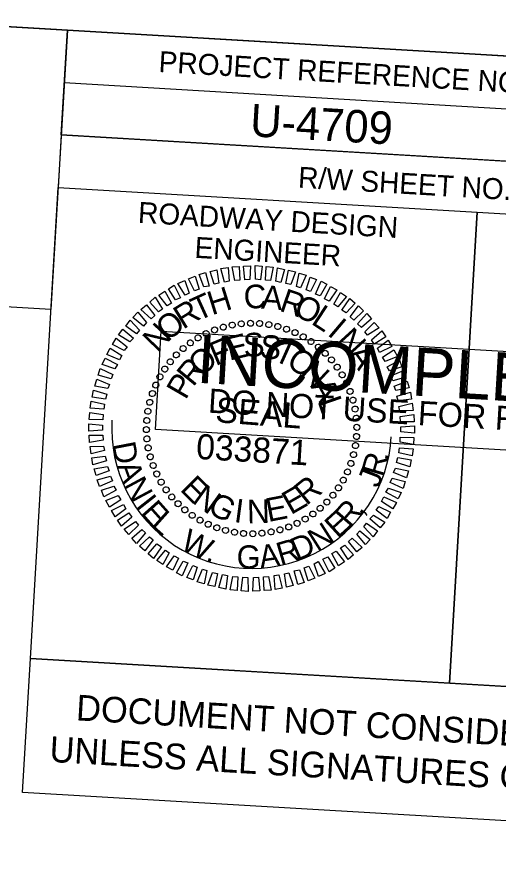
# Model space of a CAD drawing. Extents: x 2012250 to 2014096, y 444445 to 445643.
# Drawn here: x 2013858 to 2013972.6, y 445331.9 to 445534.5 of the extents above; entities that cross this region are included whole.
import ezdxf

# ---------------------------------------------------------------- set-up
doc = ezdxf.new("R2010")
doc.units = 0
for name, color, linetype in [('Old_Level_45', 7, 'Continuous'), ('Old_Level_58', 7, 'Continuous'), ('Scratch_Level_0', 7, 'Continuous'), ('Sheet Data Text CELL', 7, 'Continuous'), ('Sheet Professional Seal CELL', 7, 'Continuous'), ('Sheet Profile Grid Minor CELL', 7, 'Continuous'), ('Sheet Sticker Exception Certification CELL', 7, 'Continuous'), ('Sheet Sticker Incomplete CELL', 7, 'Continuous')]:
    doc.layers.add(name, color=color, linetype=linetype)

msp = doc.modelspace()

# ---------------------------------------------------------------- linework, layer by layer
at = {"layer": 'Old_Level_45'}
for p, q in [((2013869.23, 445518.85), (2014068.93, 445507.08)), ((2013868.5, 445506.37), (2013867.76, 445493.89)), ((2013868.5, 445506.37), (2014068.2, 445494.6)), ((2013967.64, 445488), (2013961.02, 445375.75))]:
    msp.add_line(p, q, dxfattribs=at)
for points in [[(2014069.67, 445519.6), (2012572.27, 445607.87), (2012510.48, 444559.69), (2014007.88, 444471.42)], [(2013869.97, 445531.38), (2014069.67, 445519.6), (2014068.2, 445494.6), (2013868.5, 445506.37)], [(2013867.76, 445493.89), (2013967.64, 445488), (2013961.02, 445375.7), (2013861.14, 445381.59)], [(2013967.64, 445488), (2014067.46, 445482.12), (2014060.84, 445369.81), (2013961.02, 445375.7)]]:
    msp.add_lwpolyline(points, close=True, dxfattribs=at)
at = {"layer": 'Old_Level_58'}
msp.add_lwpolyline([(2013670.27, 445543.15), (2013869.97, 445531.38), (2013866.05, 445464.8), (2013666.34, 445476.57)], close=True, dxfattribs=at)
at = {"layer": 'Scratch_Level_0'}
msp.add_arc((2013913.88, 445436.42), 33.36, 176.6264, 356.6264, dxfattribs=at)
at = {"layer": 'Sheet Professional Seal CELL'}
for p, q in [((2013905.05, 445459.93), (2013905.05, 445459.93)), ((2013907.09, 445460.61), (2013907.09, 445460.61)), ((2013909.23, 445461.09), (2013909.23, 445461.09)), ((2013911.45, 445461.36), (2013911.45, 445461.36)), ((2013913.61, 445461.53), (2013913.61, 445461.53)), ((2013915.81, 445461.45), (2013915.81, 445461.45)), ((2013918, 445461.17), (2013918, 445461.17)), ((2013920.12, 445460.7), (2013920.12, 445460.7)), ((2013922.19, 445460.12), (2013922.19, 445460.12)), ((2013901.08, 445458.01), (2013901.08, 445458.01)), ((2013903.04, 445459.05), (2013903.04, 445459.05)), ((2013924.25, 445459.3), (2013924.25, 445459.3)), ((2013926.19, 445458.28), (2013926.19, 445458.28)), ((2013899.26, 445456.87), (2013899.26, 445456.87)), ((2013928.08, 445457.17), (2013928.08, 445457.17)), ((2013895.94, 445454.01), (2013895.94, 445454.01)), ((2013897.52, 445455.47), (2013897.52, 445455.47)), ((2013929.8, 445455.82), (2013929.8, 445455.82)), ((2013931.47, 445454.37), (2013931.47, 445454.37)), ((2013894.49, 445452.34), (2013894.49, 445452.34)), ((2013932.93, 445452.78), (2013932.93, 445452.78)), ((2013893.13, 445450.62), (2013893.13, 445450.62)), ((2013934.33, 445451.04), (2013934.33, 445451.04)), ((2013892.02, 445448.73), (2013892.02, 445448.73)), ((2013935.47, 445449.22), (2013935.47, 445449.22)), ((2013891, 445446.78), (2013891, 445446.78)), ((2013936.51, 445447.26), (2013936.51, 445447.26)), ((2013890.18, 445444.73), (2013890.18, 445444.73)), ((2013937.39, 445445.25), (2013937.39, 445445.25)), ((2013889.61, 445442.66), (2013889.61, 445442.66)), ((2013938.07, 445443.21), (2013938.07, 445443.21)), ((2013889.13, 445440.53), (2013889.13, 445440.53)), ((2013938.55, 445441.08), (2013938.55, 445441.08)), ((2013888.85, 445438.35), (2013888.85, 445438.35)), ((2013938.82, 445438.86), (2013938.82, 445438.86)), ((2013888.77, 445436.15), (2013888.77, 445436.15)), ((2013913.88, 445436.42), (2013913.88, 445436.42)), ((2013938.99, 445436.69), (2013938.99, 445436.69)), ((2013888.95, 445433.98), (2013888.95, 445433.98)), ((2013938.91, 445434.49), (2013938.91, 445434.49)), ((2013889.22, 445431.76), (2013889.22, 445431.76)), ((2013938.63, 445432.31), (2013938.63, 445432.31)), ((2013889.69, 445429.63), (2013889.69, 445429.63)), ((2013938.16, 445430.18), (2013938.16, 445430.18)), ((2013890.37, 445427.59), (2013890.37, 445427.59)), ((2013937.58, 445428.11), (2013937.58, 445428.11)), ((2013891.26, 445425.58), (2013891.26, 445425.58)), ((2013936.76, 445426.06), (2013936.76, 445426.06)), ((2013892.29, 445423.62), (2013892.29, 445423.62)), ((2013935.75, 445424.11), (2013935.75, 445424.11)), ((2013893.44, 445421.8), (2013893.44, 445421.8)), ((2013934.63, 445422.22), (2013934.63, 445422.22)), ((2013894.84, 445420.06), (2013894.84, 445420.06)), ((2013933.28, 445420.5), (2013933.28, 445420.5)), ((2013896.3, 445418.47), (2013896.3, 445418.47)), ((2013930.24, 445417.37), (2013930.24, 445417.37)), ((2013931.83, 445418.83), (2013931.83, 445418.83)), ((2013897.96, 445417.02), (2013897.96, 445417.02)), ((2013899.69, 445415.67), (2013899.69, 445415.67)), ((2013928.5, 445415.97), (2013928.5, 445415.97)), ((2013901.57, 445414.56), (2013901.57, 445414.56)), ((2013903.52, 445413.54), (2013903.52, 445413.54)), ((2013924.72, 445413.79), (2013924.72, 445413.79)), ((2013926.68, 445414.83), (2013926.68, 445414.83)), ((2013905.57, 445412.72), (2013905.57, 445412.72)), ((2013907.64, 445412.15), (2013907.64, 445412.15)), ((2013909.77, 445411.67), (2013909.77, 445411.67)), ((2013911.96, 445411.39), (2013911.96, 445411.39)), ((2013914.16, 445411.31), (2013914.16, 445411.31)), ((2013916.32, 445411.48), (2013916.32, 445411.48)), ((2013918.54, 445411.75), (2013918.54, 445411.75)), ((2013920.67, 445412.23), (2013920.67, 445412.23)), ((2013922.71, 445412.91), (2013922.71, 445412.91))]:
    msp.add_line(p, q, dxfattribs=at)
for points in [[(2013904.99, 445470.8), (2013904.02, 445473.87), (2013905.59, 445474.22), (2013906.06, 445471.09)], [(2013907.42, 445471.31), (2013906.56, 445474.52), (2013908.28, 445474.77), (2013908.49, 445471.5)], [(2013909.85, 445471.72), (2013909.24, 445474.96), (2013910.9, 445475.01), (2013911.06, 445471.8)], [(2013912.27, 445471.88), (2013911.91, 445475.1), (2013913.61, 445475.2), (2013913.47, 445471.96)], [(2013914.78, 445471.98), (2013914.72, 445475.24), (2013916.36, 445475.09), (2013915.97, 445471.86)], [(2013917.17, 445471.79), (2013917.36, 445475.03), (2013919, 445474.89), (2013918.36, 445471.67)], [(2013919.66, 445471.49), (2013920.05, 445474.72), (2013921.68, 445474.33), (2013920.84, 445471.22)], [(2013922.03, 445470.95), (2013922.67, 445474.12), (2013924.3, 445473.77), (2013923.22, 445470.73)], [(2013900.24, 445469.23), (2013898.81, 445472.12), (2013900.4, 445472.73), (2013901.36, 445469.61)], [(2013902.5, 445470.15), (2013901.37, 445473.12), (2013902.9, 445473.63), (2013903.76, 445470.37)], [(2013924.54, 445470.25), (2013925.23, 445473.47), (2013926.91, 445472.97), (2013925.57, 445469.94)], [(2013926.9, 445469.46), (2013927.83, 445472.51), (2013929.35, 445471.92), (2013927.93, 445469.05)], [(2013895.75, 445467.04), (2013894.06, 445469.69), (2013895.41, 445470.57), (2013896.89, 445467.57)], [(2013898.02, 445468.16), (2013896.33, 445470.96), (2013897.93, 445471.67), (2013899.01, 445468.7)], [(2013929.09, 445468.43), (2013930.43, 445471.51), (2013931.79, 445470.83), (2013930.22, 445468.01)], [(2013931.28, 445467.35), (2013932.7, 445470.22), (2013934.21, 445469.43), (2013932.35, 445466.74)], [(2013893.77, 445465.65), (2013891.76, 445468.18), (2013893.17, 445469.15), (2013894.75, 445466.25)], [(2013933.51, 445466.07), (2013935.03, 445468.83), (2013936.47, 445467.9), (2013934.42, 445465.41)], [(2013891.68, 445464.22), (2013889.61, 445466.55), (2013890.88, 445467.68), (2013892.67, 445464.87)], [(2013935.38, 445464.6), (2013937.3, 445467.4), (2013938.53, 445466.27), (2013936.44, 445463.94)], [(2013888.07, 445460.78), (2013885.59, 445462.88), (2013886.76, 445464.11), (2013888.82, 445461.64)], [(2013889.93, 445462.58), (2013887.5, 445464.77), (2013888.82, 445465.85), (2013890.78, 445463.33)], [(2013937.34, 445462.99), (2013939.34, 445465.62), (2013940.58, 445464.45), (2013938.24, 445462.23)], [(2013886.46, 445458.97), (2013883.87, 445460.83), (2013884.9, 445462.22), (2013887.17, 445459.88)], [(2013939.14, 445461.33), (2013941.34, 445463.8), (2013942.47, 445462.53), (2013940.05, 445460.52)], [(2013884.85, 445457.06), (2013882.14, 445458.73), (2013883.22, 445460.07), (2013885.7, 445457.92)], [(2013940.84, 445459.47), (2013943.12, 445461.69), (2013944.25, 445460.42), (2013941.54, 445458.63)], [(2013883.52, 445454.99), (2013880.75, 445456.4), (2013881.59, 445457.91), (2013884.18, 445455.9)], [(2013942.48, 445457.57), (2013944.9, 445459.68), (2013945.87, 445458.28), (2013943.12, 445456.53)], [(2013943.86, 445455.54), (2013946.43, 445457.49), (2013947.29, 445455.99), (2013944.4, 445454.56)], [(2013882.39, 445452.75), (2013879.36, 445454.08), (2013880.2, 445455.59), (2013882.95, 445453.82)], [(2013945.04, 445453.42), (2013947.79, 445455.16), (2013948.65, 445453.6), (2013945.68, 445452.38)], [(2013881.26, 445450.61), (2013878.22, 445451.7), (2013878.96, 445453.2), (2013881.87, 445451.63)], [(2013946.2, 445451.14), (2013949.1, 445452.73), (2013949.66, 445451.14), (2013946.75, 445450.16)], [(2013880.37, 445448.26), (2013877.31, 445449.09), (2013877.76, 445450.72), (2013880.83, 445449.29)], [(2013947.08, 445448.94), (2013950.11, 445450.26), (2013950.66, 445448.63), (2013947.51, 445447.81)], [(2013879.58, 445445.91), (2013876.51, 445446.49), (2013876.96, 445448.16), (2013880.04, 445446.93)], [(2013947.84, 445446.54), (2013950.96, 445447.66), (2013951.42, 445446.08), (2013948.27, 445445.46)], [(2013879.03, 445443.38), (2013875.85, 445443.87), (2013876.15, 445445.56), (2013879.35, 445444.57)], [(2013948.49, 445444.1), (2013951.76, 445445.06), (2013951.96, 445443.39), (2013948.78, 445443.03)], [(2013878.64, 445441), (2013875.4, 445441.29), (2013875.6, 445442.93), (2013878.81, 445442.19)], [(2013948.95, 445441.67), (2013952.15, 445442.43), (2013952.35, 445440.71), (2013949.19, 445440.6)], [(2013878.44, 445438.51), (2013875.19, 445438.55), (2013875.29, 445440.25), (2013878.51, 445439.71)], [(2013949.26, 445439.24), (2013952.55, 445439.75), (2013952.59, 445438.04), (2013949.39, 445438.03)], [(2013878.35, 445436.01), (2013875.08, 445435.8), (2013875.08, 445437.51), (2013878.32, 445437.21)], [(2013949.42, 445436.83), (2013952.69, 445437.04), (2013952.69, 445435.33), (2013949.45, 445435.63)], [(2013878.5, 445433.6), (2013875.22, 445433.09), (2013875.17, 445434.8), (2013878.38, 445434.81)], [(2013949.32, 445434.33), (2013952.57, 445434.29), (2013952.47, 445432.59), (2013949.25, 445433.13)], [(2013878.81, 445431.17), (2013875.61, 445430.41), (2013875.41, 445432.13), (2013878.58, 445432.24)], [(2013949.12, 445431.84), (2013952.36, 445431.55), (2013952.17, 445429.91), (2013948.95, 445430.65)], [(2013879.27, 445428.74), (2013876.01, 445427.78), (2013875.81, 445429.45), (2013878.98, 445429.81)], [(2013948.73, 445429.46), (2013951.91, 445428.97), (2013951.61, 445427.28), (2013948.41, 445428.27)], [(2013879.93, 445426.3), (2013876.81, 445425.18), (2013876.35, 445426.76), (2013879.49, 445427.38)], [(2013948.18, 445426.94), (2013951.25, 445426.35), (2013950.81, 445424.68), (2013947.72, 445425.91)], [(2013880.69, 445423.9), (2013877.65, 445422.58), (2013877.1, 445424.21), (2013880.25, 445425.03)], [(2013947.39, 445424.58), (2013950.45, 445423.75), (2013950, 445422.12), (2013946.93, 445423.55)], [(2013881.56, 445421.7), (2013878.66, 445420.11), (2013878.1, 445421.7), (2013881.02, 445422.68)], [(2013946.5, 445422.23), (2013949.55, 445421.15), (2013948.81, 445419.64), (2013945.89, 445421.21)], [(2013882.73, 445419.42), (2013879.97, 445417.68), (2013879.11, 445419.24), (2013882.09, 445420.46)], [(2013945.38, 445420.09), (2013948.4, 445418.76), (2013947.56, 445417.26), (2013944.81, 445419.02)], [(2013883.91, 445417.3), (2013881.34, 445415.35), (2013880.47, 445416.85), (2013883.36, 445418.28)], [(2013944.24, 445417.85), (2013947.01, 445416.44), (2013946.17, 445414.93), (2013943.59, 445416.94)], [(2013885.29, 445415.27), (2013882.86, 445413.16), (2013881.89, 445414.56), (2013884.65, 445416.31)], [(2013942.92, 445415.78), (2013945.62, 445414.11), (2013944.54, 445412.77), (2013942.07, 445414.92)], [(2013886.93, 445413.37), (2013884.64, 445411.15), (2013883.52, 445412.42), (2013886.23, 445414.21)], [(2013941.3, 445413.87), (2013943.9, 445412.01), (2013942.86, 445410.62), (2013940.6, 445412.96)], [(2013888.62, 445411.51), (2013886.42, 445409.04), (2013885.3, 445410.31), (2013887.72, 445412.32)], [(2013939.69, 445412.06), (2013942.17, 445409.96), (2013941, 445408.73), (2013938.94, 445411.2)], [(2013890.43, 445409.85), (2013888.42, 445407.22), (2013887.19, 445408.39), (2013889.52, 445410.61)], [(2013937.83, 445410.27), (2013940.26, 445408.07), (2013938.94, 445406.99), (2013936.99, 445409.51)], [(2013892.39, 445408.24), (2013890.47, 445405.44), (2013889.23, 445406.57), (2013891.32, 445408.9)], [(2013894.25, 445406.77), (2013892.74, 445404.01), (2013891.29, 445404.95), (2013893.34, 445407.43)], [(2013936.08, 445408.62), (2013938.15, 445406.29), (2013936.88, 445405.16), (2013935.09, 445407.97)], [(2013896.48, 445405.49), (2013895.06, 445402.62), (2013893.55, 445403.41), (2013895.42, 445406.1)], [(2013932.01, 445405.8), (2013933.71, 445403.15), (2013932.35, 445402.27), (2013930.88, 445405.27)], [(2013934, 445407.19), (2013936, 445404.66), (2013934.59, 445403.69), (2013933.01, 445406.59)], [(2013898.67, 445404.41), (2013897.34, 445401.33), (2013895.98, 445402.01), (2013897.54, 445404.83)], [(2013900.87, 445403.38), (2013899.93, 445400.33), (2013898.42, 445400.92), (2013899.84, 445403.79)], [(2013927.53, 445403.61), (2013928.96, 445400.72), (2013927.37, 445400.11), (2013926.4, 445403.23)], [(2013929.74, 445404.68), (2013931.43, 445401.88), (2013929.84, 445401.17), (2013928.76, 445404.14)], [(2013903.22, 445402.59), (2013902.53, 445399.37), (2013900.86, 445399.87), (2013902.19, 445402.9)], [(2013905.74, 445401.89), (2013905.1, 445398.72), (2013903.47, 445399.07), (2013904.55, 445402.11)], [(2013908.11, 445401.35), (2013907.72, 445398.12), (2013906.09, 445398.51), (2013906.92, 445401.62)], [(2013910.6, 445401.05), (2013910.4, 445397.81), (2013908.76, 445397.96), (2013909.4, 445401.17)], [(2013920.34, 445401.53), (2013921.2, 445398.32), (2013919.49, 445398.07), (2013919.28, 445401.34)], [(2013922.77, 445402.04), (2013923.75, 445398.97), (2013922.17, 445398.62), (2013921.71, 445401.75)], [(2013925.27, 445402.69), (2013926.39, 445399.72), (2013924.86, 445399.21), (2013924, 445402.47)], [(2013912.99, 445400.86), (2013913.05, 445397.6), (2013911.4, 445397.75), (2013911.79, 445400.98)], [(2013915.5, 445400.96), (2013915.86, 445397.74), (2013914.15, 445397.64), (2013914.29, 445400.88)], [(2013917.91, 445401.12), (2013918.52, 445397.88), (2013916.87, 445397.83), (2013916.71, 445401.04)]]:
    msp.add_lwpolyline(points, close=True, dxfattribs=at)
for centre, major_axis in [((2013911.42, 445461.38), (-0.071, 0.717)), ((2013913.61, 445461.5), (-0.008, 0.72)), ((2013915.79, 445461.43), (0.055, 0.718)), ((2013917.97, 445461.17), (0.117, 0.71)), ((2013905.05, 445459.89), (-0.254, 0.674)), ((2013907.13, 445460.57), (-0.194, 0.693)), ((2013909.26, 445461.07), (-0.133, 0.708)), ((2013920.11, 445460.72), (0.179, 0.697)), ((2013922.2, 445460.08), (0.239, 0.679)), ((2013924.23, 445459.26), (0.297, 0.656)), ((2013901.11, 445458), (-0.367, 0.62)), ((2013903.04, 445459.03), (-0.311, 0.649)), ((2013926.18, 445458.28), (0.353, 0.627)), ((2013928.04, 445457.12), (0.407, 0.594)), ((2013897.55, 445455.46), (-0.469, 0.546)), ((2013899.27, 445456.81), (-0.419, 0.585)), ((2013929.79, 445455.81), (0.457, 0.557)), ((2013895.96, 445453.96), (-0.515, 0.504)), ((2013931.42, 445454.35), (0.504, 0.515)), ((2013894.49, 445452.33), (-0.557, 0.457)), ((2013932.92, 445452.75), (0.546, 0.469)), ((2013934.27, 445451.03), (0.585, 0.419)), ((2013893.18, 445450.58), (-0.594, 0.407)), ((2013935.46, 445449.2), (0.62, 0.367)), ((2013892.03, 445448.72), (-0.627, 0.353)), ((2013936.5, 445447.27), (0.649, 0.311)), ((2013891.04, 445446.77), (-0.656, 0.297)), ((2013937.35, 445445.26), (0.674, 0.254)), ((2013890.22, 445444.74), (-0.679, 0.239)), ((2013938.04, 445443.18), (0.693, 0.194)), ((2013889.59, 445442.65), (-0.697, 0.179)), ((2013938.53, 445441.05), (0.708, 0.133)), ((2013889.14, 445440.51), (-0.71, 0.117)), ((2013938.84, 445438.88), (0.717, 0.071)), ((2013888.88, 445438.33), (-0.718, 0.055)), ((2013888.8, 445436.15), (-0.72, -0.008)), ((2013938.96, 445436.69), (0.72, 0.008)), ((2013888.92, 445433.96), (-0.717, -0.071)), ((2013938.89, 445434.51), (0.718, -0.055)), ((2013889.23, 445431.8), (-0.708, -0.133)), ((2013938.63, 445432.34), (0.71, -0.117)), ((2013889.73, 445429.66), (-0.693, -0.194)), ((2013938.18, 445430.19), (0.697, -0.179)), ((2013890.41, 445427.59), (-0.674, -0.254)), ((2013937.54, 445428.1), (0.679, -0.239)), ((2013891.27, 445425.57), (-0.649, -0.311)), ((2013936.73, 445426.07), (0.656, -0.297)), ((2013892.3, 445423.64), (-0.62, -0.367)), ((2013935.74, 445424.12), (0.627, -0.353)), ((2013893.5, 445421.81), (-0.585, -0.419)), ((2013934.58, 445422.26), (0.594, -0.407)), ((2013894.85, 445420.09), (-0.546, -0.469)), ((2013931.81, 445418.88), (0.515, -0.504)), ((2013933.27, 445420.51), (0.557, -0.457)), ((2013896.34, 445418.49), (-0.504, -0.515)), ((2013897.97, 445417.03), (-0.457, -0.557)), ((2013930.21, 445417.39), (0.469, -0.546)), ((2013899.72, 445415.72), (-0.407, -0.594)), ((2013901.58, 445414.56), (-0.353, -0.627)), ((2013926.66, 445414.84), (0.367, -0.62)), ((2013928.49, 445416.03), (0.419, -0.585)), ((2013903.53, 445413.58), (-0.297, -0.656)), ((2013905.56, 445412.76), (-0.239, -0.679)), ((2013922.72, 445412.95), (0.254, -0.674)), ((2013924.73, 445413.81), (0.311, -0.649)), ((2013907.66, 445412.13), (-0.179, -0.697)), ((2013909.8, 445411.68), (-0.117, -0.71)), ((2013911.97, 445411.41), (-0.055, -0.718)), ((2013914.16, 445411.34), (0.008, -0.72)), ((2013916.34, 445411.46), (0.071, -0.717)), ((2013918.51, 445411.77), (0.133, -0.708)), ((2013920.64, 445412.27), (0.194, -0.693))]:
    msp.add_ellipse(centre, major_axis=major_axis, ratio=0.999708, dxfattribs=at)
at = {"layer": 'Sheet Sticker Exception Certification CELL'}
for p, q in [((2013859.26, 445349.68), (2013861.14, 445381.6)), ((2013861.14, 445381.6), (2014060.84, 445369.83)), ((2014058.96, 445337.91), (2013859.26, 445349.68))]:
    msp.add_line(p, q, dxfattribs=at)
at = {"layer": 'Sheet Sticker Incomplete CELL'}
msp.add_lwpolyline([(2013890.95, 445436.18), (2013892.34, 445459.64), (2014039.08, 445450.99), (2014037.7, 445427.53)], close=True, dxfattribs=at)

# ---------------------------------------------------------------- texts
at = {"layer": 'Old_Level_45'}
for s, height, p in [('PROJECT REFERENCE NO.', 5.0001, (2013891.62, 445521.39)), ('R/W SHEET NO.', 5.0001, (2013924.86, 445493.83)), ('ROADWAY DESIGN', 5.0001, (2013886.7, 445485.46)), ('ENGINEER', 5, (2013900.18, 445477.11))]:
    msp.add_text(s, height=height, rotation=356.6264, dxfattribs=at).set_placement(p)
at = {"layer": 'Sheet Data Text CELL'}
msp.add_text('U-4709', height=7.75, rotation=356.6264, dxfattribs=at).set_placement((2013913.36, 445506.08))
at = {"layer": 'Sheet Professional Seal CELL'}
for s, height, rotation, p in [('H', 5.64, 17.2459, (2013904.4, 445463.37)), ('C', 5.64, 2.8463, (2013912.11, 445464.92)), ('A', 5.64, 355.6467, (2013916.07, 445464.99)), ('T', 5.64, 24.4462, (2013901.06, 445461.92)), ('R', 5.64, 341.2475, (2013920.25, 445464.54)), ('O', 5.64, 334.0476, (2013923.55, 445463.6)), ('R', 5.64, 31.6469, (2013897.54, 445459.92)), ('O', 5.64, 38.8482, (2013893.91, 445457.03)), ('L', 5.64, 326.8473, (2013927.83, 445461.49)), ('I', 5.64, 319.6466, (2013931.73, 445458.86)), ('N', 5.64, 46.0499, (2013891.44, 445454.27)), ('N', 5.64, 312.4453, (2013933.79, 445457.18)), ('F', 5.64, 22.5935, (2013905.29, 445451.25)), ('E', 5.64, 13.2375, (2013908.57, 445452.56)), ('S', 5.64, 3.882, (2013912.08, 445453.41)), ('S', 5.64, 354.5268, (2013915.68, 445453.24)), ('I', 5.64, 335.816, (2013919.93, 445452.29)), ('O', 5.64, 41.3077, (2013901.82, 445448.5)), ('O', 5.64, 326.4599, (2013921.88, 445451.48)), ('A', 5.64, 305.2436, (2013936.56, 445454.07)), ('R', 5.64, 50.6661, (2013899.93, 445446.16)), ('N', 5.64, 317.103, (2013925.11, 445449.28)), ('P', 5.64, 60.0253, (2013898.15, 445443.06)), ('A', 5.64, 298.3867, (2013927.8, 445446.52)), ('SEAL', 5.998, 355.6264, (2013905.11, 445437.94)), ('L', 5.64, 289.0273, (2013929.54, 445442.96)), ('E', 5.64, 314.9033, (2013896.59, 445421.76)), ('R', 5.64, 39.1078, (2013926.91, 445417.87)), ('N', 5.64, 324.2604, (2013899.43, 445418.89)), ('E', 5.64, 29.7505, (2013923.23, 445415.73)), ('G', 5.64, 333.6167, (2013903.09, 445416.42)), ('I', 5.64, 352.3276, (2013909.51, 445414.14)), ('N', 5.64, 1.6828, (2013912.85, 445413.79)), ('E', 5.64, 11.0382, (2013917.83, 445414.1))]:
    msp.add_text(s, height=height, rotation=rotation, dxfattribs=at).set_placement(p)
at = {"layer": 'Sheet Profile Grid Minor CELL'}
for s, height, rotation, p in [('033871', 5.998, 356.6264, (2013900.53, 445429.18)), ('D', 5.5, 280.8946, (2013880.62, 445432.73)), ('R', 5.5, 73.9805, (2013945.22, 445424.65)), ('.', 5.5, 80.9069, (2013946.41, 445428.52)), ('A', 5.5, 290.0393, (2013881.63, 445427.49)), ('J', 5.5, 69.1119, (2013944.1, 445422.04)), ('N', 5.5, 298.2251, (2013883.23, 445422.99)), ('I', 5.5, 308.1568, (2013886, 445417.9)), ('E', 5.5, 311.6772, (2013887.19, 445416.22)), ('R', 5.5, 49.0052, (2013937.32, 445412.52)), ('L', 5.5, 318.2602, (2013889.68, 445413.3)), ('E', 5.5, 42.4222, (2013934.42, 445410)), (',', 5.5, 55.9317, (2013940.03, 445415.52)), ('N', 5.5, 32.4905, (2013929.56, 445406.85)), ('W', 5.5, 333.5156, (2013896.62, 445407.75)), ('R', 5.5, 16.4194, (2013920.76, 445403.66)), ('D', 5.5, 23.3459, (2013924.66, 445404.73)), ('G', 5.5, 358.3019, (2013910.23, 445403.15)), ('A', 5.5, 8.2337, (2013916.03, 445403.02)), ('.', 5.5, 345.1217, (2013902.74, 445404.86))]:
    msp.add_text(s, height=height, rotation=rotation, dxfattribs=at).set_placement(p)
at = {"layer": 'Sheet Sticker Exception Certification CELL'}
for s, p in [('DOCUMENT NOT CONSIDERED FINAL', (2013871.92, 445366.87)), ('UNLESS ALL SIGNATURES COMPLETED', (2013865.59, 445356.96))]:
    msp.add_text(s, height=6.124, rotation=356.6264, dxfattribs=at).set_placement(p)
at = {"layer": 'Sheet Sticker Incomplete CELL'}
for s, height, p in [('INCOMPLETE PLANS', 11.52, (2013900.58, 445447.33)), ('DO NOT USE FOR R/W ACQUISITION', 5.76, (2013903.41, 445440.2))]:
    msp.add_text(s, height=height, rotation=356.6264, dxfattribs=at).set_placement(p)

doc.saveas('drawing.dxf')
